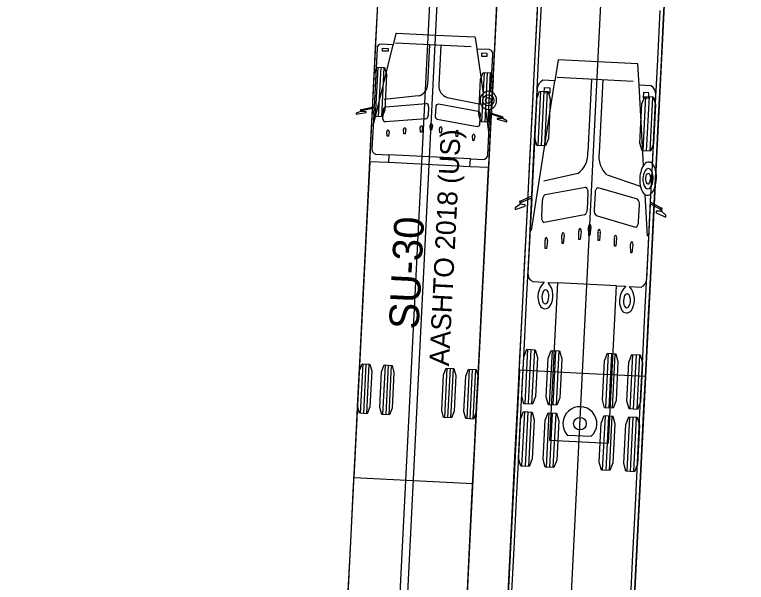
# Model space of a CAD drawing. Extents: x 260275 to 261282, y 610916 to 614143.
# Drawn here: x 261035.48 to 261084.72, y 612414.03 to 612452.24 of the extents above; entities that cross this region are included whole.
import ezdxf

# ---------------------------------------------------------------- set-up
doc = ezdxf.new("R2010")
doc.units = 0
doc.layers.add('GE_X_Alignment', color=7, linetype='Continuous')
doc.layers.add('TopoDOT_Transients', color=7, linetype='Continuous')

msp = doc.modelspace()

# ---------------------------------------------------------------- linework, layer by layer
at = {"layer": 'GE_X_Alignment'}
msp.add_line((260986.249, 610915.954), (261148.276, 614142.838), dxfattribs=at)
at = {"layer": 'TopoDOT_Transients'}
for p, q in [((261059.045, 612136.423), (261081.046, 612574.591)), ((261048.059, 612136.974), (261068.197, 612538.052)), ((261059.607, 612444.745), (261060.948, 612450.212)), ((261066.202, 612450.072), (261061.104, 612450.328)), ((261063.404, 612450.212), (261063.27, 612447.547)), ((261064.168, 612450.174), (261064.035, 612447.509)), ((261060.237, 612449.792), (261060.247, 612449.986)), ((261060.615, 612449.773), (261060.237, 612449.792)), ((261060.247, 612449.986), (261060.625, 612449.967)), ((261060.625, 612449.967), (261060.615, 612449.773)), ((261067.03, 612446.962), (261066.611, 612449.928)), ((261066.909, 612449.651), (261066.899, 612449.457)), ((261067.287, 612449.632), (261066.909, 612449.651)), ((261067.277, 612449.438), (261067.287, 612449.632)), ((261067.533, 612447.053), (261067.66, 612449.572)), ((261066.899, 612449.457), (261067.277, 612449.438)), ((261077.425, 612448.932), (261072.061, 612449.201)), ((261059.915, 612448.707), (261059.748, 612445.378)), ((261060.123, 612448.697), (261059.956, 612445.368)), ((261060.331, 612448.686), (261060.164, 612445.357)), ((261067.073, 612448.348), (261066.905, 612445.019)), ((261067.281, 612448.337), (261067.113, 612445.008)), ((261067.489, 612448.327), (261067.322, 612444.998)), ((261070.268, 612437.715), (261071.84, 612447.784)), ((261077.1, 612447.745), (261072.001, 612448.001)), ((261074.301, 612447.886), (261074.055, 612443)), ((261075.065, 612447.847), (261074.82, 612442.962)), ((261070.868, 612447.091), (261070.685, 612443.429)), ((261071.097, 612447.08), (261070.913, 612443.418)), ((261071.11, 612446.984), (261071.128, 612447.339)), ((261071.128, 612447.339), (261071.506, 612447.32)), ((261071.326, 612447.068), (261071.142, 612443.406)), ((261071.506, 612447.32), (261071.488, 612446.965)), ((261077.799, 612442.086), (261077.503, 612447.499)), ((261062.631, 612446.771), (261060.353, 612446.54)), ((261064.592, 612446.673), (261066.847, 612446.212)), ((261071.488, 612446.965), (261071.11, 612446.984)), ((261077.943, 612446.736), (261077.759, 612443.074)), ((261077.79, 612447.005), (261077.772, 612446.649)), ((261077.772, 612446.649), (261078.15, 612446.63)), ((261078.168, 612446.986), (261077.79, 612447.005)), ((261078.172, 612446.725), (261077.988, 612443.063)), ((261078.15, 612446.63), (261078.168, 612446.986)), ((261078.401, 612446.713), (261078.217, 612443.051)), ((261078.403, 612442.189), (261078.639, 612446.884)), ((261060.46, 612446.041), (261063.168, 612446.257)), ((261066.679, 612445.729), (261064.006, 612446.215)), ((261060.267, 612445.231), (261060.298, 612445.847)), ((261063.34, 612446.047), (261063.309, 612445.431)), ((261063.815, 612446.023), (261063.784, 612445.407)), ((261067.398, 612444.354), (261067.181, 612445.887)), ((261063.147, 612445.236), (261060.439, 612445.02)), ((261063.925, 612445.197), (261066.598, 612444.711)), ((261066.79, 612444.904), (261066.821, 612445.52)), ((261062.802, 612444.341), (261062.781, 612444.642)), ((261062.935, 612444.635), (261062.884, 612444.337)), ((261063.458, 612444.477), (261063.437, 612444.778)), ((261063.591, 612444.77), (261063.54, 612444.472)), ((261064.097, 612444.276), (261064.076, 612444.577)), ((261060.55, 612444.061), (261060.53, 612444.362)), ((261060.684, 612444.354), (261060.633, 612444.057)), ((261061.677, 612444.215), (261061.656, 612444.53)), ((261061.759, 612444.211), (261061.677, 612444.215)), ((261061.81, 612444.522), (261061.759, 612444.211)), ((261062.884, 612444.337), (261062.802, 612444.341)), ((261063.54, 612444.472), (261063.458, 612444.477)), ((261064.179, 612444.272), (261064.097, 612444.276)), ((261064.23, 612444.569), (261064.179, 612444.272)), ((261065.203, 612444.038), (261065.182, 612444.339)), ((261065.337, 612444.331), (261065.286, 612444.034)), ((261060.633, 612444.057), (261060.55, 612444.061)), ((261065.286, 612444.034), (261065.203, 612444.038)), ((261066.309, 612443.772), (261066.288, 612444.073)), ((261066.391, 612443.768), (261066.309, 612443.772)), ((261066.442, 612444.065), (261066.391, 612443.768)), ((261066.151, 612442.538), (261060.666, 612442.814)), ((261066.124, 612442.007), (261060.639, 612442.283)), ((261073.383, 612441.553), (261071.09, 612441.034)), ((261075.344, 612441.454), (261077.585, 612440.705)), ((261071.177, 612440.125), (261073.9, 612440.634)), ((261074.063, 612440.255), (261074.006, 612439.125)), ((261074.538, 612440.231), (261074.481, 612439.102)), ((261077.396, 612439.813), (261074.738, 612440.592)), ((261070.95, 612438.633), (261071.007, 612439.763)), ((261078.059, 612437.324), (261077.906, 612440.124)), ((261069.496, 612439.483), (261069.475, 612439.468)), ((261069.522, 612439.481), (261069.496, 612439.483)), ((261077.472, 612438.306), (261077.529, 612439.435)), ((261073.836, 612438.763), (261071.113, 612438.255)), ((261074.614, 612438.724), (261077.272, 612437.945)), ((261078.978, 612439.006), (261079.004, 612439.006)), ((261079.004, 612439.006), (261079.024, 612438.988)), ((261074.115, 612437.385), (261074.107, 612437.935)), ((261074.261, 612437.928), (261074.198, 612437.381)), ((261072.32, 612436.831), (261072.312, 612437.407)), ((261072.466, 612437.399), (261072.402, 612436.827)), ((261073.452, 612437.109), (261073.444, 612437.66)), ((261073.598, 612437.652), (261073.535, 612437.105)), ((261074.198, 612437.381), (261074.115, 612437.385)), ((261074.747, 612437.044), (261074.739, 612437.595)), ((261074.893, 612437.587), (261074.83, 612437.04)), ((261075.846, 612436.654), (261075.838, 612437.205)), ((261075.992, 612437.197), (261075.929, 612436.65)), ((261071.185, 612436.502), (261071.176, 612437.053)), ((261071.331, 612437.045), (261071.267, 612436.498)), ((261072.402, 612436.827), (261072.32, 612436.831)), ((261073.535, 612437.105), (261073.452, 612437.109)), ((261074.83, 612437.04), (261074.747, 612437.044)), ((261076.943, 612436.213), (261076.935, 612436.764)), ((261077.089, 612436.756), (261077.025, 612436.209)), ((261071.267, 612436.498), (261071.185, 612436.502)), ((261075.929, 612436.65), (261075.846, 612436.654)), ((261077.025, 612436.209), (261076.943, 612436.213)), ((261070.346, 612434.268), (261071.12, 612434.229)), ((261075.975, 612433.985), (261072.007, 612434.185)), ((261076.862, 612433.941), (261077.636, 612433.902)), ((261069.996, 612429.713), (261069.812, 612426.051)), ((261070.225, 612429.702), (261070.041, 612426.04)), ((261070.454, 612429.69), (261070.27, 612426.028)), ((261071.644, 612429.631), (261071.46, 612425.968)), ((261071.873, 612429.619), (261071.689, 612425.957)), ((261072.102, 612429.608), (261071.918, 612425.945)), ((261075.422, 612429.441), (261075.239, 612425.779)), ((261075.651, 612429.429), (261075.467, 612425.767)), ((261075.88, 612429.418), (261075.696, 612425.756)), ((261077.07, 612429.358), (261076.886, 612425.696)), ((261077.299, 612429.347), (261077.115, 612425.685)), ((261077.528, 612429.335), (261077.344, 612425.673)), ((261058.912, 612428.732), (261058.745, 612425.403)), ((261059.12, 612428.722), (261058.953, 612425.393)), ((261059.328, 612428.711), (261059.161, 612425.382)), ((261060.41, 612428.657), (261060.243, 612425.328)), ((261060.618, 612428.647), (261060.451, 612425.317)), ((261060.826, 612428.636), (261060.659, 612425.307)), ((261064.571, 612428.448), (261064.404, 612425.119)), ((261064.78, 612428.438), (261064.612, 612425.109)), ((261064.988, 612428.427), (261064.82, 612425.098)), ((261066.07, 612428.373), (261065.902, 612425.044)), ((261066.278, 612428.362), (261066.111, 612425.033)), ((261066.486, 612428.352), (261066.319, 612425.023)), ((261069.785, 612425.519), (261069.601, 612421.856)), ((261070.014, 612425.507), (261069.83, 612421.845)), ((261070.243, 612425.496), (261070.059, 612421.834)), ((261071.433, 612425.436), (261071.249, 612421.774)), ((261071.662, 612425.424), (261071.478, 612421.762)), ((261071.891, 612425.413), (261071.707, 612421.751)), ((261075.212, 612425.246), (261075.028, 612421.584)), ((261075.441, 612425.235), (261075.257, 612421.573)), ((261075.67, 612425.223), (261075.486, 612421.561)), ((261076.86, 612425.163), (261076.676, 612421.501)), ((261077.089, 612425.152), (261076.905, 612421.49)), ((261077.317, 612425.14), (261077.134, 612421.478)), ((261072.673, 612423.942), (261074.287, 612423.861))]:
    msp.add_line(p, q, dxfattribs=at)
for points in [[(261051.548, 612071.863), (261074.206, 612523.277)], [(261082.631, 612521.243), (261060.03, 612071.291)], [(261042.767, 612111.356), (261063.016, 612514.614)], [(261070.923, 612512.551), (261050.75, 612110.806)], [(261077.141, 612412.069), (261077.308, 612415.399), (261077.475, 612418.729), (261077.642, 612422.058), (261077.81, 612425.388), (261077.977, 612428.717), (261078.144, 612432.047), (261078.311, 612435.376), (261078.478, 612438.706), (261078.646, 612442.035), (261078.813, 612445.365), (261078.98, 612448.694), (261079.147, 612452.024), (261079.314, 612455.354)], [(261057.935, 612413.436), (261058.102, 612416.764), (261058.27, 612420.093), (261058.437, 612423.421), (261058.604, 612426.749), (261058.771, 612430.078), (261058.938, 612433.406), (261059.105, 612436.735), (261059.272, 612440.063), (261059.439, 612443.392), (261059.607, 612446.72), (261059.774, 612450.049), (261059.941, 612453.377)], [(261057.935, 612413.432), (261058.102, 612416.76), (261058.269, 612420.088), (261058.436, 612423.417), (261058.604, 612426.745), (261058.771, 612430.074), (261058.938, 612433.402), (261059.105, 612436.731), (261059.272, 612440.059), (261059.439, 612443.388), (261059.606, 612446.716), (261059.773, 612450.044), (261059.941, 612453.373)], [(261065.925, 612413.035), (261066.092, 612416.363), (261066.259, 612419.691), (261066.427, 612423.02), (261066.594, 612426.348), (261066.761, 612429.677), (261066.928, 612433.005), (261067.095, 612436.334), (261067.262, 612439.662), (261067.429, 612442.991), (261067.596, 612446.319), (261067.764, 612449.647), (261067.931, 612452.976)], [(261065.925, 612413.03), (261066.092, 612416.359), (261066.259, 612419.687), (261066.426, 612423.016), (261066.594, 612426.344), (261066.761, 612429.673), (261066.928, 612433.001), (261067.095, 612436.329), (261067.262, 612439.658), (261067.429, 612442.986), (261067.596, 612446.315), (261067.763, 612449.643), (261067.931, 612452.972)], [(261068.926, 612412.975), (261069.093, 612416.305), (261069.26, 612419.634), (261069.428, 612422.964), (261069.595, 612426.293), (261069.762, 612429.623), (261069.929, 612432.953), (261070.096, 612436.282), (261070.263, 612439.612), (261070.431, 612442.941), (261070.598, 612446.271), (261070.765, 612449.6), (261070.932, 612452.93)], [(261076.916, 612412.574), (261077.083, 612415.904), (261077.25, 612419.233), (261077.417, 612422.563), (261077.585, 612425.892), (261077.752, 612429.222), (261077.919, 612432.551), (261078.086, 612435.881), (261078.253, 612439.21), (261078.421, 612442.54), (261078.588, 612445.87), (261078.755, 612449.199), (261078.922, 612452.529)], [(261068.652, 612412.496), (261068.819, 612415.825), (261068.986, 612419.155), (261069.153, 612422.484), (261069.32, 612425.814), (261069.488, 612429.143), (261069.655, 612432.473), (261069.822, 612435.803), (261069.989, 612439.132), (261070.156, 612442.462), (261070.323, 612445.791), (261070.491, 612449.121), (261070.658, 612452.45)], [(261067.422, 612449.887), (261066.615, 612449.928), (261066.611, 612449.933), (261066.501, 612450.711), (261066.459, 612450.715), (261063.819, 612450.847), (261061.179, 612450.98), (261061.136, 612450.98), (261060.949, 612450.217), (261060.944, 612450.213), (261060.138, 612450.253)], [(261059.869, 612449.963), (261059.672, 612446.035), (261059.665, 612446.024), (261058.823, 612445.839), (261058.822, 612445.839)], [(261077.425, 612448.932), (261072.061, 612449.201), (261071.84, 612447.784), (261071.026, 612447.824)], [(261078.317, 612447.458), (261077.503, 612447.499), (261077.426, 612448.919)], [(261070.649, 612447.285), (261070.284, 612440.017), (261069.527, 612439.686)], [(261058.778, 612445.768), (261058.775, 612445.721), (261058.775, 612445.721), (261058.474, 612445.604), (261058.47, 612445.539), (261058.473, 612445.539), (261059.135, 612445.645), (261059.138, 612445.646), (261059.141, 612445.702), (261059.139, 612445.702), (261058.822, 612445.727), (261058.822, 612445.727), (261058.824, 612445.771)], [(261058.837, 612445.791), (261058.837, 612445.791), (261059.664, 612445.969), (261059.668, 612445.957), (261059.529, 612443.186)], [(261067.319, 612442.795), (261067.459, 612445.566), (261067.464, 612445.578), (261068.269, 612445.317), (261068.269, 612445.317)], [(261068.289, 612445.364), (261068.288, 612445.364), (261067.469, 612445.632), (261067.462, 612445.644), (261067.474, 612445.872)], [(261068.28, 612445.297), (261068.278, 612445.252), (261068.278, 612445.252), (261067.96, 612445.259), (261067.958, 612445.259), (261067.955, 612445.204), (261067.958, 612445.202), (261068.606, 612445.03), (261068.609, 612445.03), (261068.612, 612445.095), (261068.324, 612445.241), (261068.324, 612445.242), (261068.325, 612445.289)], [(261059.768, 612442.859), (261060.663, 612442.814), (261060.666, 612442.81), (261060.639, 612442.284), (261060.628, 612442.283), (261059.387, 612442.345), (261058.319, 612421.086), (261062.314, 612420.885), (261066.309, 612420.684), (261067.377, 612441.944), (261066.135, 612442.007), (261066.124, 612442.008), (261066.151, 612442.534), (261066.154, 612442.538), (261067.049, 612442.493)], [(261078.993, 612439.211), (261078.274, 612439.616), (261078.303, 612440.189)], [(261069.54, 612439.599), (261069.54, 612439.599), (261070.279, 612439.918), (261070.024, 612434.843)], [(261069.48, 612439.555), (261069.475, 612439.468), (261069.168, 612439.242), (261069.162, 612439.122), (261069.836, 612439.346), (261069.841, 612439.449), (261069.522, 612439.481), (261069.527, 612439.562)], [(261078.014, 612434.441), (261078.269, 612439.517), (261078.972, 612439.125), (261078.972, 612439.125)], [(261078.982, 612439.088), (261078.978, 612439.006), (261078.657, 612439.006), (261078.652, 612438.903), (261079.3, 612438.613), (261079.306, 612438.733), (261079.024, 612438.988), (261079.027, 612439.075)], [(261071.377, 612434.216), (261072.007, 612434.185), (261071.475, 612423.598), (261075.444, 612423.399), (261075.975, 612433.985), (261076.605, 612433.954)], [(261075.509, 612380.012), (261075.531, 612380.01), (261077.935, 612427.88), (261073.69, 612428.093), (261069.445, 612428.306), (261067.042, 612380.437), (261067.064, 612380.436)]]:
    msp.add_lwpolyline(points, dxfattribs=at)
for points in [[(261059.863, 612448.71), (261060.383, 612448.684), (261060.516, 612448.21), (261060.395, 612445.813), (261060.215, 612445.355), (261059.696, 612445.381), (261059.563, 612445.855), (261059.683, 612448.252)], [(261067.021, 612448.35), (261067.54, 612448.324), (261067.673, 612447.85), (261067.553, 612445.453), (261067.373, 612444.995), (261066.854, 612445.021), (261066.721, 612445.495), (261066.841, 612447.892)], [(261070.812, 612447.094), (261071.383, 612447.066), (261071.529, 612446.544), (261071.397, 612443.908), (261071.199, 612443.403), (261070.628, 612443.432), (261070.481, 612443.954), (261070.614, 612446.59)], [(261077.886, 612446.739), (261078.457, 612446.71), (261078.604, 612446.189), (261078.471, 612443.552), (261078.274, 612443.048), (261077.702, 612443.077), (261077.556, 612443.598), (261077.688, 612446.235)], [(261069.939, 612429.716), (261070.51, 612429.687), (261070.657, 612429.166), (261070.524, 612426.529), (261070.327, 612426.025), (261069.755, 612426.054), (261069.609, 612426.575), (261069.741, 612429.212)], [(261071.587, 612429.633), (261072.158, 612429.605), (261072.305, 612429.083), (261072.172, 612426.447), (261071.974, 612425.943), (261071.403, 612425.971), (261071.257, 612426.493), (261071.389, 612429.129)], [(261075.366, 612429.444), (261075.937, 612429.415), (261076.083, 612428.894), (261075.951, 612426.257), (261075.753, 612425.753), (261075.182, 612425.782), (261075.035, 612426.303), (261075.168, 612428.94)], [(261077.014, 612429.361), (261077.585, 612429.332), (261077.731, 612428.811), (261077.599, 612426.174), (261077.401, 612425.67), (261076.83, 612425.699), (261076.683, 612426.22), (261076.816, 612428.857)], [(261058.86, 612428.735), (261059.38, 612428.709), (261059.513, 612428.235), (261059.392, 612425.838), (261059.213, 612425.38), (261058.693, 612425.406), (261058.56, 612425.88), (261058.68, 612428.277)], [(261060.358, 612428.66), (261060.878, 612428.634), (261061.011, 612428.16), (261060.891, 612425.763), (261060.711, 612425.304), (261060.191, 612425.331), (261060.058, 612425.804), (261060.179, 612428.201)], [(261064.52, 612428.451), (261065.039, 612428.425), (261065.172, 612427.951), (261065.052, 612425.554), (261064.872, 612425.096), (261064.353, 612425.122), (261064.22, 612425.596), (261064.34, 612427.992)], [(261066.018, 612428.375), (261066.537, 612428.349), (261066.67, 612427.875), (261066.55, 612425.479), (261066.37, 612425.02), (261065.851, 612425.046), (261065.718, 612425.52), (261065.838, 612427.917)], [(261069.729, 612425.521), (261070.3, 612425.493), (261070.446, 612424.971), (261070.314, 612422.335), (261070.116, 612421.831), (261069.545, 612421.859), (261069.398, 612422.381), (261069.531, 612425.017)], [(261071.376, 612425.439), (261071.948, 612425.41), (261072.094, 612424.889), (261071.962, 612422.252), (261071.764, 612421.748), (261071.193, 612421.777), (261071.046, 612422.298), (261071.179, 612424.935)], [(261075.155, 612425.249), (261075.726, 612425.22), (261075.873, 612424.699), (261075.74, 612422.062), (261075.542, 612421.558), (261074.971, 612421.587), (261074.825, 612422.108), (261074.957, 612424.745)], [(261076.803, 612425.166), (261077.374, 612425.137), (261077.521, 612424.616), (261077.388, 612421.979), (261077.19, 612421.475), (261076.619, 612421.504), (261076.473, 612422.025), (261076.605, 612424.662)]]:
    msp.add_lwpolyline(points, close=True, dxfattribs=at)
for centre, radius in [((261067.359, 612446.47), 0.374), ((261067.359, 612446.47), 0.193), ((261073.52, 612424.709), 0.424)]:
    msp.add_circle(centre, radius, dxfattribs=at)
for centre, radius, start, end in [((261060.151, 612449.972), 0.282, 92.6739, 181.7533), ((261067.38, 612449.609), 0.282, 352.4977, 81.5771), ((261062.497, 612447.533), 0.773, 280.016, 1.1001), ((261071.427, 612447.142), 0.792, 120.4366, 169.5921), ((261064.802, 612447.417), 0.773, 173.1509, 254.235), ((261067.363, 612446.556), 0.526, 71.0707, 129.3167), ((261067.291, 612446.473), 0.628, 286.8788, 67.3705), ((261077.85, 612446.82), 0.792, 4.6589, 53.8144), ((261067.427, 612446.474), 0.629, 129.1711, 177.8604), ((261063.157, 612446.073), 0.184, 351.6672, 86.5274), ((261063.999, 612446.031), 0.184, 87.7236, 182.5838), ((261067.427, 612446.459), 0.63, 176.4803, 228.8831), ((261058.801, 612445.803), 0.0418, 59.6174, 236.6324), ((261058.795, 612445.803), 0.0434, 312.5392, 343.212), ((261060.491, 612445.851), 0.193, 99.2679, 181.1824), ((261066.63, 612445.543), 0.193, 353.0686, 74.9831), ((261067.354, 612446.383), 0.524, 229.3845, 283.1846), ((261060.45, 612445.204), 0.184, 171.6617, 266.5329), ((261063.116, 612445.427), 0.193, 279.263, 1.1873), ((261063.975, 612445.383), 0.193, 173.0637, 254.988), ((261068.312, 612445.326), 0.0434, 191.039, 221.7118), ((261068.306, 612445.326), 0.0418, 297.6187, 114.6336), ((261061.746, 612444.53), 0.091, 94.6451, 188.8089), ((261061.722, 612444.531), 0.0909, 345.4064, 79.6416), ((261062.871, 612444.656), 0.091, 94.6451, 188.8089), ((261062.847, 612444.657), 0.0909, 345.4064, 79.6416), ((261063.527, 612444.792), 0.091, 94.6451, 188.8089), ((261063.503, 612444.793), 0.091, 345.4421, 79.6059), ((261064.166, 612444.591), 0.0909, 94.6094, 188.8446), ((261064.142, 612444.592), 0.091, 345.4421, 79.6059), ((261066.606, 612444.895), 0.184, 267.7181, 2.5893), ((261060.62, 612444.376), 0.091, 94.6451, 188.8089), ((261060.596, 612444.377), 0.0909, 345.4064, 79.6416), ((261065.272, 612444.353), 0.0909, 94.6094, 188.8446), ((261065.249, 612444.354), 0.091, 345.4421, 79.6059), ((261066.378, 612444.087), 0.0909, 94.6094, 188.8446), ((261066.354, 612444.088), 0.091, 345.4421, 79.6059), ((261059.852, 612443.17), 0.323, 177.1255, 254.9739), ((261066.997, 612442.812), 0.323, 279.2771, 357.1255), ((261072.429, 612442.875), 1.631, 305.8013, 4.3921), ((261076.425, 612442.675), 1.631, 169.8589, 228.4497), ((261078.677, 612441.467), 1.074, 138.5821, 162.851), ((261078.167, 612441.938), 0.38, 90.4559, 140.9794), ((261078.142, 612441.991), 0.328, 37.2138, 86.1182), ((261077.885, 612441.691), 0.719, 15.6559, 43.9129), ((261079.595, 612441.134), 2.049, 161.5065, 177.4318), ((261078.863, 612441.182), 1.098, 150.3913, 178.2839), ((261078.152, 612441.615), 0.268, 92.1981, 155.8758), ((261078.011, 612441.497), 0.407, 8.3561, 71.1606), ((261076.938, 612441.329), 1.731, 3.5106, 18.7084), ((261079.556, 612441.112), 2.012, 176.7669, 195.4498), ((261078.674, 612441.118), 0.914, 173.9599, 216.0179), ((261078.547, 612441.176), 0.617, 169.4131, 202.6039), ((261078.21, 612441.294), 0.27, 108.2744, 181.0182), ((261078.05, 612441.344), 0.22, 8.1354, 69.8336), ((261077.654, 612441.225), 0.631, 330.9338, 13.7343), ((261077.537, 612441.169), 0.913, 320.4351, 0.6954), ((261077.218, 612441.25), 1.234, 356.7552, 14.3373), ((261076.467, 612441.283), 2.204, 344.3246, 3.9597), ((261078.095, 612440.964), 0.12, 192.1016, 337.5796), ((261077.684, 612440.875), 0.924, 312.0226, 348.3008), ((261073.728, 612440.341), 0.342, 348.7273, 58.6538), ((261074.879, 612440.284), 0.342, 115.5972, 185.5237), ((261078.395, 612440.755), 0.799, 192.9249, 232.1926), ((261078.068, 612440.377), 0.301, 237.3568, 321.2551), ((261078.085, 612440.711), 0.199, 220.9288, 321.5681), ((261069.591, 612439.617), 0.127, 145.0209, 209.2301), ((261069.506, 612439.675), 0.0244, 27.9931, 141.3075), ((261071.409, 612439.795), 0.403, 125.1252, 184.5832), ((261077.132, 612439.508), 0.403, 349.6678, 49.1258), ((261069.431, 612439.617), 0.11, 330.073, 350.1813), ((261079.014, 612439.197), 0.0244, 32.9435, 146.2579), ((261078.923, 612439.148), 0.127, 325.0209, 29.2301), ((261073.609, 612439.089), 0.397, 304.8867, 3.0497), ((261074.872, 612439.026), 0.397, 171.2013, 229.3643), ((261079.082, 612439.133), 0.11, 184.0697, 204.178), ((261071.275, 612438.546), 0.334, 168.2627, 240.8606), ((261077.14, 612438.251), 0.334, 293.3904, 5.9883), ((261073.634, 612437.692), 0.192, 122.2012, 189.6758), ((261073.413, 612437.703), 0.192, 344.5479, 52.0772), ((261074.297, 612437.968), 0.192, 122.2012, 189.6758), ((261074.076, 612437.979), 0.192, 344.5752, 52.0498), ((261074.928, 612437.627), 0.192, 122.1738, 189.7031), ((261074.708, 612437.638), 0.192, 344.5752, 52.0498), ((261071.366, 612437.085), 0.192, 122.2012, 189.6758), ((261071.145, 612437.096), 0.192, 344.5479, 52.0772), ((261072.501, 612437.414), 0.192, 122.2012, 189.6758), ((261072.281, 612437.425), 0.192, 344.5479, 52.0772), ((261076.027, 612437.237), 0.192, 122.1738, 189.7031), ((261075.807, 612437.248), 0.192, 344.5752, 52.0498), ((261077.124, 612436.796), 0.192, 122.1738, 189.7031), ((261076.903, 612436.807), 0.192, 344.5752, 52.0498), ((261070.592, 612434.783), 0.571, 174.0409, 244.4325), ((261077.443, 612434.439), 0.571, 289.8185, 0.2101), ((261072.039, 612433.249), 1.344, 133.1609, 206.7157), ((261070.364, 612433.333), 1.344, 327.5353, 41.0901), ((261077.524, 612432.974), 1.344, 133.1609, 206.7157), ((261075.849, 612433.058), 1.344, 327.5353, 41.0901), ((261071.824, 612433.22), 0.86, 158.6915, 198.6609), ((261071.297, 612433.438), 0.29, 104.7698, 160.9298), ((261071.161, 612433.479), 0.247, 5.5291, 75.4082), ((261070.556, 612433.282), 0.879, 339.9934, 14.5886), ((261076.746, 612433.199), 0.247, 98.8428, 168.7219), ((261076.607, 612433.171), 0.29, 13.3212, 69.4812), ((261071.23, 612433.002), 0.228, 194.4278, 256.3226), ((261071.127, 612433.038), 0.262, 280.9175, 347.4427), ((261077.328, 612432.942), 0.879, 159.6624, 194.2576), ((261076.061, 612433.007), 0.86, 335.5901, 15.5595), ((261071.179, 612432.831), 0.387, 208.621, 325.63), ((261076.663, 612432.547), 0.383, 207.5963, 326.6547), ((261076.736, 612432.756), 0.262, 186.8083, 253.3335), ((261076.63, 612432.731), 0.228, 277.9284, 339.8232), ((261073.52, 612424.709), 1.143, 312.1255, 222.1255)]:
    msp.add_arc(centre, radius, start, end, dxfattribs=at)
for centre, major_axis, start_param, end_param in [((261069.503, 612439.621), (0.0039, 0.0781), 4.442794, 5.713538), ((261069.503, 612439.621), (-0.0039, -0.0781), 5.756759, 7.026061), ((261079.011, 612439.144), (-0.0039, -0.0781), 3.71124, 4.981984), ((261079.011, 612439.144), (0.0039, 0.0781), 2.398717, 3.668019)]:
    msp.add_ellipse(centre, major_axis=major_axis, ratio=0.5, start_param=start_param, end_param=end_param, dxfattribs=at)

# ---------------------------------------------------------------- texts
for s, height, p in [('AASHTO 2018 (US)', 1.33333, (261064.709, 612428.56)), ('SU-30', 2, (261062.663, 612431.023))]:
    msp.add_text(s, height=height, rotation=87.1255, dxfattribs=at).set_placement(p)

doc.saveas('drawing.dxf')
